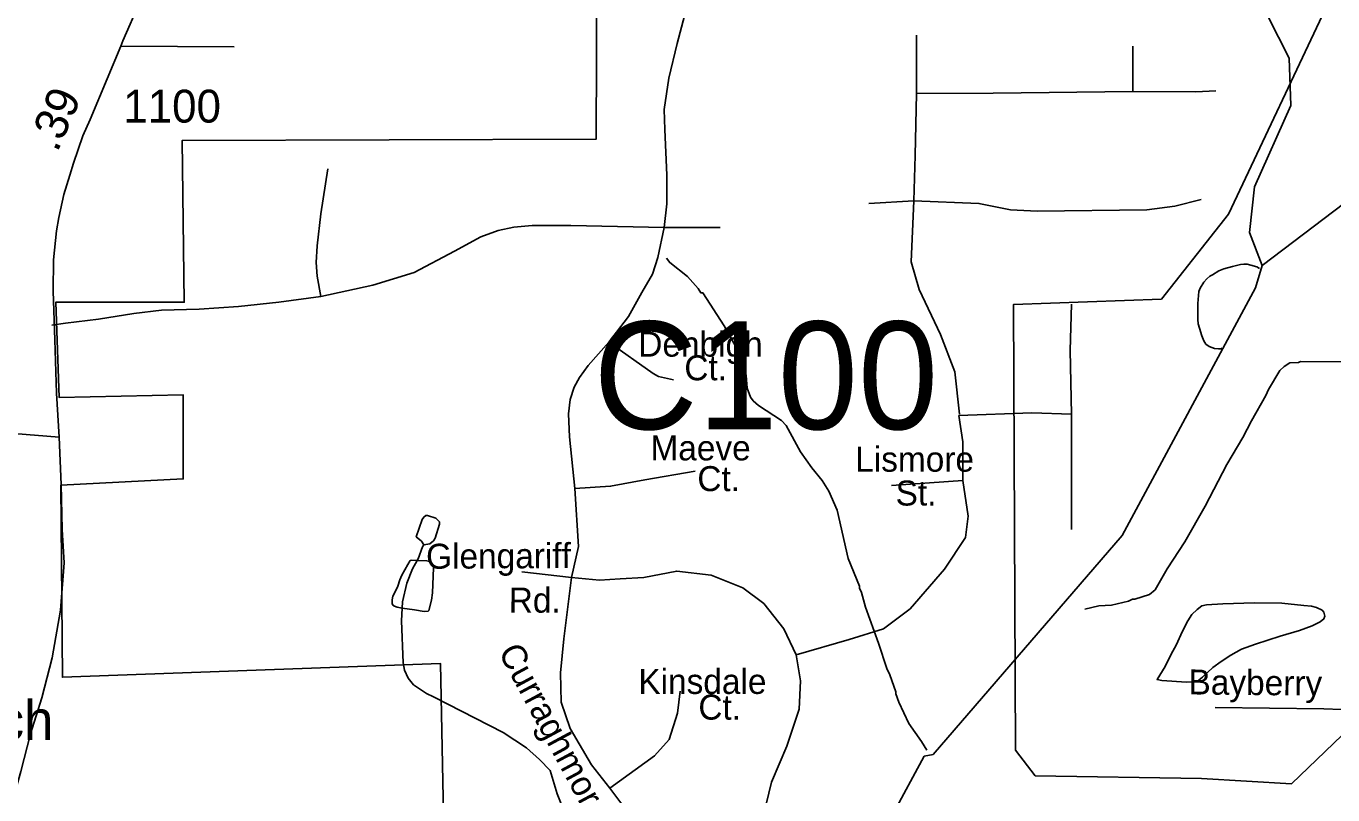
# Model space of a CAD drawing. Extents: x 1547597 to 1699558, y 810033 to 920809.
# Drawn here: x 1580417 to 1585386, y 836281 to 839204 of the extents above; entities that cross this region are included whole.
import ezdxf

# ---------------------------------------------------------------- set-up
doc = ezdxf.new("R2010")
doc.units = 0
for name, color, linetype in [('Exist Boundary Political City Limit New', 7, 'Continuous'), ('Exist Cultural Church with Cemetery Label', 7, 'Continuous'), ('Exist Hydrographic Creek Single Shore', 7, 'Continuous'), ('Exist Hydrographic Misc Water Feature', 7, 'Continuous'), ('Exist Road Non-System Type 51', 7, 'Continuous'), ('Exist Road Non-System Type 51 Label', 7, 'Continuous'), ('Exist Road Secondary Mileage Hundredths English Label', 7, 'Continuous'), ('Exist Road Secondary Structure Culvert Number Label', 7, 'Continuous'), ('Exist Road Secondary Type 51 Attributed', 7, 'Continuous'), ('Exist Road Secondary Type 51 Number Label', 7, 'Continuous'), ('Map Preparation Boundary City Limit Buffer Line', 7, 'Continuous')]:
    doc.layers.add(name, color=color, linetype=linetype)

msp = doc.modelspace()

# ---------------------------------------------------------------- linework, layer by layer
at = {"layer": 'Exist Boundary Political City Limit New'}
for points in [[(1584886.8, 836342.8), (1584254.2, 836353), (1584179.2, 836450.6), (1584171.7, 838145.2), (1584734, 838165.7), (1584989, 838488.6), (1585379, 839314.3), (1584930.3, 839508.1), (1583543.6, 839509.2), (1583551.1, 839261.5), (1583228.6, 839239), (1583229.7, 840648.8), (1582592.2, 840678.8), (1582585, 838774.6), (1581010.5, 838769.3), (1581018, 838153.8), (1580529.8, 838154.6), (1580542, 837792.4), (1581014.3, 837801.6), (1581014.3, 837482.5), (1580548.2, 837457.9), (1580554.3, 836728.2), (1581993, 836780), (1582030.8, 834859.6)], [(1585644.7, 836721.7), (1585229.2, 836322.9), (1584886.8, 836342.8)]]:
    msp.add_lwpolyline(points, dxfattribs=at)
at = {"layer": 'Exist Hydrographic Creek Single Shore'}
for points in [[(1585117.5, 838293.2), (1585547.6, 838619.3), (1585792.5, 838867), (1585903.6, 839032.3), (1586217.5, 839393.6), (1586397.5, 839767.4), (1586761.5, 840718.6), (1586859.5, 841126.9), (1586879.5, 841970.2), (1586957.5, 842238.7), (1586986.8, 842579.1), (1586985.5, 842926.6), (1587021.2, 843660.8), (1587109.6, 843958.2), (1587214.6, 844349.9), (1587369.6, 844655.4), (1587407.5, 844969.8), (1587404.6, 845370.3), (1587343.5, 845755.6), (1587421.6, 845980.6), (1587450.6, 846262.3), (1587508.6, 847345.1)], [(1585117.5, 838293.2), (1585069.5, 838418.9), (1585088.6, 838592.5), (1585226.6, 838901.5), (1585220.5, 839082.2), (1585139.5, 839241.4), (1585065.5, 839328.3), (1584960.5, 839563.5), (1584898.5, 839820.7), (1584861.6, 840163), (1584821.5, 840304.9), (1584651.5, 840616.9), (1584587.5, 840802.1), (1584516.5, 841135.1), (1584420.5, 841370.1), (1584415.5, 841580.2), (1584326.5, 841831.5), (1584071.5, 842059.9), (1583966.5, 842278.7), (1583843.5, 842445.4)], [(1583831.5, 836428.4), (1583865.6, 836434.3), (1584585.6, 837266.6), (1585091.6, 838208.3), (1585117.5, 838293.2)], [(1582991.5, 832538.9), (1583025.6, 832577.7), (1583027.5, 832728.7), (1582946.5, 832864.9), (1582956.6, 833005.8), (1583227.8, 833980.6), (1583257.2, 834111.1), (1583361.5, 834168.2), (1583441.4, 834277.5), (1583511.5, 834432.4), (1583602.6, 834962.3), (1583667.6, 836011.5), (1583711.6, 836204.3), (1583831.5, 836428.4)]]:
    msp.add_lwpolyline(points, dxfattribs=at)
at = {"layer": 'Exist Hydrographic Misc Water Feature'}
msp.add_line((1584963.7, 837980.2), (1584962.9, 837977), dxfattribs=at)
for points in [[(1582852.4, 838321.3), (1582864.2, 838305.1), (1582931.5, 838252.3), (1582973, 838205.8), (1582982.8, 838189.7), (1582990.8, 838189.6), (1583071.3, 838064.6), (1583132, 837955.9), (1583143.6, 837923.8), (1583155.1, 837875.7), (1583158.4, 837827.6), (1583172.1, 837793.5), (1583181.9, 837779.3), (1583201.7, 837761.2), (1583289, 837704), (1583306.8, 837685.8), (1583361.5, 837585.2), (1583404.8, 837524.7), (1583444.3, 837476.2), (1583469.8, 837435.9), (1583500.9, 837363.6), (1583542.7, 837179.1), (1583585.5, 837074.6), (1583585.4, 837066.6), (1583593.1, 837050.5), (1583608.5, 836994.4), (1583658.9, 836857.8), (1583689.7, 836761.4), (1583701.4, 836737.3), (1583724.7, 836673), (1583724.6, 836665), (1583736.2, 836632.9), (1583773.2, 836552.5), (1583822.4, 836483.9), (1583841.8, 836451)], [(1584962.9, 837977), (1584951.2, 837976.9), (1584935.7, 837978.7), (1584916.4, 837985.3), (1584903.5, 837994.8), (1584895, 838007), (1584888.2, 838026), (1584878.9, 838055.8), (1584874.3, 838071.3), (1584872.7, 838088.8), (1584873.3, 838149.3), (1584877, 838194.8), (1584881.5, 838207.3), (1584895, 838230.3), (1584906.8, 838243.6), (1584918.2, 838252.7), (1584928.4, 838258.8), (1584952.4, 838272.9), (1584971.4, 838280.8), (1585005, 838290.3), (1585034.7, 838297.5), (1585047.8, 838299.2), (1585060.4, 838298.5), (1585074.9, 838295.4), (1585097.5, 838288.1), (1585107.5, 838281.8)], [(1585498, 837911.5), (1585455.1, 837922.7), (1585423.1, 837927.1), (1585263.2, 837929.1), (1585255.2, 837925.2), (1585223.2, 837923.7), (1585201.1, 837909.9), (1585184.9, 837894.1), (1585142, 837822.7), (1585131.8, 837798.8), (1585076.6, 837703.6), (1585043.9, 837640), (1584982.7, 837536.8), (1584900.8, 837378), (1584823.2, 837243), (1584756, 837139.8), (1584711, 837060.5), (1584688.8, 837042.8), (1584632.7, 837025.5), (1584624.7, 837025.6), (1584608.6, 837017.8), (1584544.4, 837002.6), (1584496.4, 836999.2), (1584442.4, 836986.5)], [(1581929.7, 837231.3), (1581951.7, 837235.1), (1581965.9, 837246.9), (1581972, 837256.8), (1581988.6, 837310.6), (1581988.7, 837318.6), (1581974.9, 837332.7), (1581943, 837343.2), (1581936.9, 837343.2), (1581928.9, 837337.3), (1581922.8, 837327.4), (1581900.2, 837262.3), (1581919.8, 837245.5), (1581929.7, 837231.3)], [(1581929.7, 837231.3), (1581923.6, 837223.5), (1581908, 837178.8), (1581904.3, 837172.3)], [(1581846.7, 836991.3), (1581827.4, 836994.4), (1581817.9, 836997.8), (1581811.3, 837002.4), (1581808.5, 837009.1), (1581808.4, 837022.7), (1581810.8, 837036.3), (1581822.9, 837057.5), (1581830.3, 837075), (1581837.7, 837098.2), (1581845.7, 837116.8), (1581868.6, 837157.3), (1581877.7, 837171.9), (1581881.8, 837173), (1581904.3, 837172.3)], [(1581904.3, 837172.3), (1581886.1, 837140), (1581864, 837086.1), (1581848.1, 837014.4), (1581846.7, 836991.3)], [(1581904.3, 837172.3), (1581940, 837171.2), (1581947.3, 837169.6), (1581957.5, 837163.5), (1581963, 837156.8), (1581965.1, 837151.5), (1581965.3, 837144.1), (1581962.6, 837049.1), (1581958.1, 837021.1), (1581947.8, 836982.2), (1581945.1, 836979.3), (1581930.8, 836978.5), (1581893.3, 836984), (1581846.7, 836991.3)], [(1584905.2, 837003.1), (1584967.6, 837006.7), (1585087.7, 837011.1), (1585192.6, 837009.2), (1585276.4, 837001.1), (1585305.7, 836998.7), (1585324.5, 836993.6), (1585345.1, 836982.9), (1585352.5, 836975.1), (1585355.2, 836960), (1585352.1, 836949.7), (1585337.7, 836938.6), (1585307.3, 836923.1), (1585259.7, 836906), (1585185.7, 836884.7), (1585092.5, 836854.2), (1585039.3, 836834.4), (1584998.3, 836812.5), (1584962, 836788.5), (1584929.4, 836764.6), (1584890.1, 836728.5), (1584870.9, 836712.7), (1584855.8, 836710.2), (1584829.3, 836709.7), (1584735.8, 836716.1), (1584718, 836719.3), (1584748.1, 836768.8), (1584770.6, 836812.8), (1584791.1, 836852.1), (1584813.6, 836900.8), (1584835.1, 836942), (1584849.7, 836966.3), (1584870.8, 836985.7), (1584888, 836999.6), (1584905.2, 837003.1)], [(1581846.7, 836991.3), (1581844.1, 836943.2), (1581851, 836783.1), (1581855.6, 836755.3), (1581869.2, 836724.9), (1581890.3, 836699.4), (1581939.1, 836666), (1581966.2, 836653.7), (1582231.1, 836517.9), (1582319.4, 836460.1), (1582368.9, 836415.9), (1582409.4, 836373.7), (1582436.3, 836285.4), (1582479, 836176.9)]]:
    msp.add_lwpolyline(points, dxfattribs=at)
at = {"layer": 'Exist Road Non-System Type 51'}
for p, q in [((1580776.4, 839127.4), (1581207.5, 839124.6)), ((1582843.6, 838438.1), (1583056.7, 838438.1))]:
    msp.add_line(p, q, dxfattribs=at)
for points in [[(1582843.6, 838438.1), (1582853.7, 838528.6), (1582853.7, 838637.5), (1582845.4, 838810.9), (1582843.6, 838886.6), (1582861.1, 839006.6), (1582892.5, 839137.6), (1582921.1, 839242.8), (1582928.5, 839314.8), (1582937.7, 839384.9)], [(1583803.2, 838948.3), (1583803.2, 839170)], [(1584626.1, 838955.6), (1584626.1, 839076.2), (1584626.1, 839127.9)], [(1583793.2, 838540.1), (1583798.2, 838711.4), (1583803.2, 838948.3)], [(1583803.2, 838948.3), (1584094.2, 838948.7), (1584626.1, 838955.6)], [(1584626.1, 838955.6), (1584865.4, 838953.9), (1584941.2, 838957.4)], [(1581536.9, 838176.1), (1581523, 838253.6), (1581519.4, 838305.3), (1581523, 838368), (1581537.8, 838489.8), (1581563.6, 838661.5)], [(1583793.2, 838540.1), (1583622, 838530)], [(1583966.6, 837728), (1583949.2, 837890), (1583893.9, 838031.1), (1583813.3, 838202.5), (1583783.1, 838308.3), (1583793.2, 838540.1)], [(1583793.2, 838540.1), (1584039.9, 838530), (1584160.7, 838504.8), (1584261.4, 838499.8), (1584679.3, 838504.8), (1584785.1, 838519.9), (1584885.8, 838545.1)], [(1581536.9, 838176.1), (1581735.3, 838218.5), (1581892.2, 838266.5), (1582046.3, 838347.7), (1582145.9, 838403.1), (1582212.4, 838427.1), (1582271.4, 838440), (1582341.6, 838445.5), (1582488.3, 838445.5), (1582843.6, 838438.1)], [(1582843.6, 838438.1), (1582818.7, 838323.7), (1582798.4, 838261), (1582757.8, 838190.8), (1582707.9, 838100.4), (1582633.2, 838002.6)], [(1580514.4, 838067.2), (1580566.1, 838074.6), (1580691.6, 838089.3), (1580826.3, 838111.5), (1580931.5, 838124.4), (1581074.6, 838128.1), (1581224.1, 838137.3), (1581378.2, 838153.9), (1581536.9, 838176.1)], [(1584392.3, 837728.8), (1584387.3, 837970.7), (1584392.3, 838147)], [(1582633.2, 838002.6), (1582553.8, 837914), (1582520.6, 837867.8), (1582500.3, 837830.9), (1582485.5, 837784.8), (1582479.1, 837729.4), (1582482.8, 837642.7), (1582503.7, 837445.5)], [(1582633.2, 838002.6), (1582801.1, 837882.6), (1582821.4, 837871.5), (1582878.6, 837858.6)], [(1583964.4, 837723.7), (1584241.3, 837733.8), (1584392.3, 837728.8)], [(1583979.5, 837476.8), (1583979.5, 837622.9), (1583964.4, 837723.7)], [(1584392.3, 837728.8), (1584392.3, 837507), (1584392.3, 837290.3)], [(1582503.7, 837445.5), (1582639.5, 837454.6), (1582770.2, 837478.2), (1582961.2, 837512.2)], [(1583345.7, 836813.5), (1583546.4, 836872.1), (1583677.3, 836912.4), (1583778.1, 836988), (1583909, 837139.1), (1583989.5, 837260.1), (1583999.6, 837340.7), (1583979.5, 837476.8)], [(1583979.5, 837476.8), (1583707.6, 837456.6)], [(1582490.6, 837107.9), (1582516.8, 837225.7), (1582503.7, 837445.5)], [(1582490.6, 837107.9), (1582302.3, 837128.8)], [(1582637, 836305.8), (1582566.4, 836394.7), (1582485.4, 836533.5), (1582451.4, 836632.9), (1582448.7, 836745.4), (1582461.8, 836873.7), (1582490.6, 837107.9)], [(1583345.7, 836813.5), (1583298.7, 836911.6), (1583222.8, 837008.5), (1583141.8, 837068.7), (1583021.5, 837115.8), (1582890.7, 837131.5), (1582765.2, 837107.9), (1582676.3, 837102.7), (1582597.8, 837097.4), (1582490.6, 837107.9)], [(1583228.1, 836131.7), (1583230.7, 836245.6), (1583251.6, 836329.3), (1583309.1, 836465.4), (1583356.2, 836606.7), (1583361.4, 836714), (1583345.7, 836813.5)], [(1582637, 836305.8), (1582807, 836428.8), (1582861.9, 836491.6), (1582893.3, 836591), (1582903.8, 836674.8)], [(1585855.8, 836357), (1585822.9, 836423.8), (1585779.4, 836462.3), (1585743.8, 836488.8), (1585674.2, 836523.9), (1585596.7, 836561.1), (1585537, 836575.9), (1585487.2, 836594.7), (1585447.3, 836601.3), (1585419.3, 836605.7), (1585351.4, 836608.6), (1584939.2, 836612.6)], [(1583228.1, 836131.7), (1583097.3, 836133), (1582932.5, 836127.8), (1582841, 836140.9), (1582754.7, 836172.3), (1582697.2, 836224.6), (1582637, 836305.8)]]:
    msp.add_lwpolyline(points, dxfattribs=at)
at = {"layer": 'Exist Road Secondary Type 51 Attributed'}
for points in [[(1580541.7, 837640.6), (1580531.7, 837808.8), (1580526.2, 838011.5), (1580518.9, 838196.6), (1580520.6, 838315), (1580532.1, 838425.7), (1580541, 838476.2), (1580560.1, 838563.4), (1580582.6, 838637.1), (1580596.1, 838682.8), (1580632, 838786.6), (1580659.7, 838849.5), (1580724.4, 839003.5), (1580776.4, 839127.4), (1580784.3, 839147.4), (1580849.3, 839294.9), (1580892.2, 839411.2), (1580940.7, 839511.1), (1580975.3, 839590.3)], [(1580541.7, 837640.6), (1579992.4, 837685.1), (1579824.5, 837687.1), (1579706.6, 837709.1), (1579404.4, 837717.4), (1578510.7, 837744.1), (1578478.7, 837744.6), (1578448.5, 837739)], [(1579939.5, 835589.6), (1580237.2, 835930.9), (1580266.8, 835970.2), (1580299.7, 836038.5), (1580345.7, 836188.4), (1580396.5, 836369.9), (1580432.7, 836513.5), (1580475.8, 836649.7), (1580515.3, 836802.2), (1580546.8, 836983.6), (1580561.3, 837163.7), (1580553.4, 837289.9), (1580549.4, 837460.7), (1580541.7, 837640.6)]]:
    msp.add_lwpolyline(points, dxfattribs=at)
at = {"layer": 'Map Preparation Boundary City Limit Buffer Line'}
for points in [[(1584886.8, 836342.8), (1584254.2, 836353), (1584179.2, 836450.6), (1584171.7, 838145.2), (1584734, 838165.7), (1584989, 838488.6), (1585379, 839314.3), (1584930.3, 839508.1), (1583543.6, 839509.2), (1583551.1, 839261.5), (1583228.6, 839239), (1583229.7, 840648.8), (1582592.2, 840678.8), (1582585, 838774.6), (1581010.5, 838769.3), (1581018, 838153.8), (1580529.8, 838154.6), (1580542, 837792.4), (1581014.3, 837801.6), (1581014.3, 837482.5), (1580548.2, 837457.9), (1580554.3, 836728.2), (1581993, 836780), (1582030.8, 834859.6)], [(1585644.7, 836721.7), (1585229.2, 836322.9), (1584886.8, 836342.8)]]:
    msp.add_lwpolyline(points, dxfattribs=at)

# ---------------------------------------------------------------- texts
at = {"layer": 'Exist Cultural Church with Cemetery Label'}
msp.add_text('Union Hill Church', height=150, dxfattribs=at).set_placement((1578959.5, 836490))
at = {"layer": 'Exist Road Non-System Type 51 Label'}
for s, p in [('Denbigh', (1582744.7, 837947.2)), ('Ct.', (1582919.8, 837857.2)), ('Maeve', (1582790.9, 837552.7)), ('Lismore', (1583569.7, 837509.7)), ('Ct.', (1582969.3, 837435.8)), ('St.', (1583723.4, 837381))]:
    msp.add_text(s, height=95, dxfattribs=at).set_placement(p)
for s, rotation, p in [('Glengariff', 0.2816, (1581937.9, 837140.5)), ('Rd.', 359.8659, (1582252, 836974)), ('Curraghmore', 298.2864, (1582210.5, 836824.7)), ('Kinsdale', 0.008, (1582744.9, 836664.6)), ('Bayberry', 359.4436, (1584837, 836662.8)), ('Ct.', 359.7227, (1582973, 836567.2))]:
    msp.add_text(s, height=95, rotation=rotation, dxfattribs=at).set_placement(p)
at = {"layer": 'Exist Road Secondary Mileage Hundredths English Label'}
msp.add_text('.39', height=125, rotation=66.2716, dxfattribs=at).set_placement((1580534.9, 838720.9))
at = {"layer": 'Exist Road Secondary Structure Culvert Number Label'}
msp.add_text('C100', height=410.1, dxfattribs=at).set_placement((1582574.3, 837671))
at = {"layer": 'Exist Road Secondary Type 51 Number Label'}
msp.add_text('1100', height=125, dxfattribs=at).set_placement((1580785.8, 838837.1))

doc.saveas('drawing.dxf')
